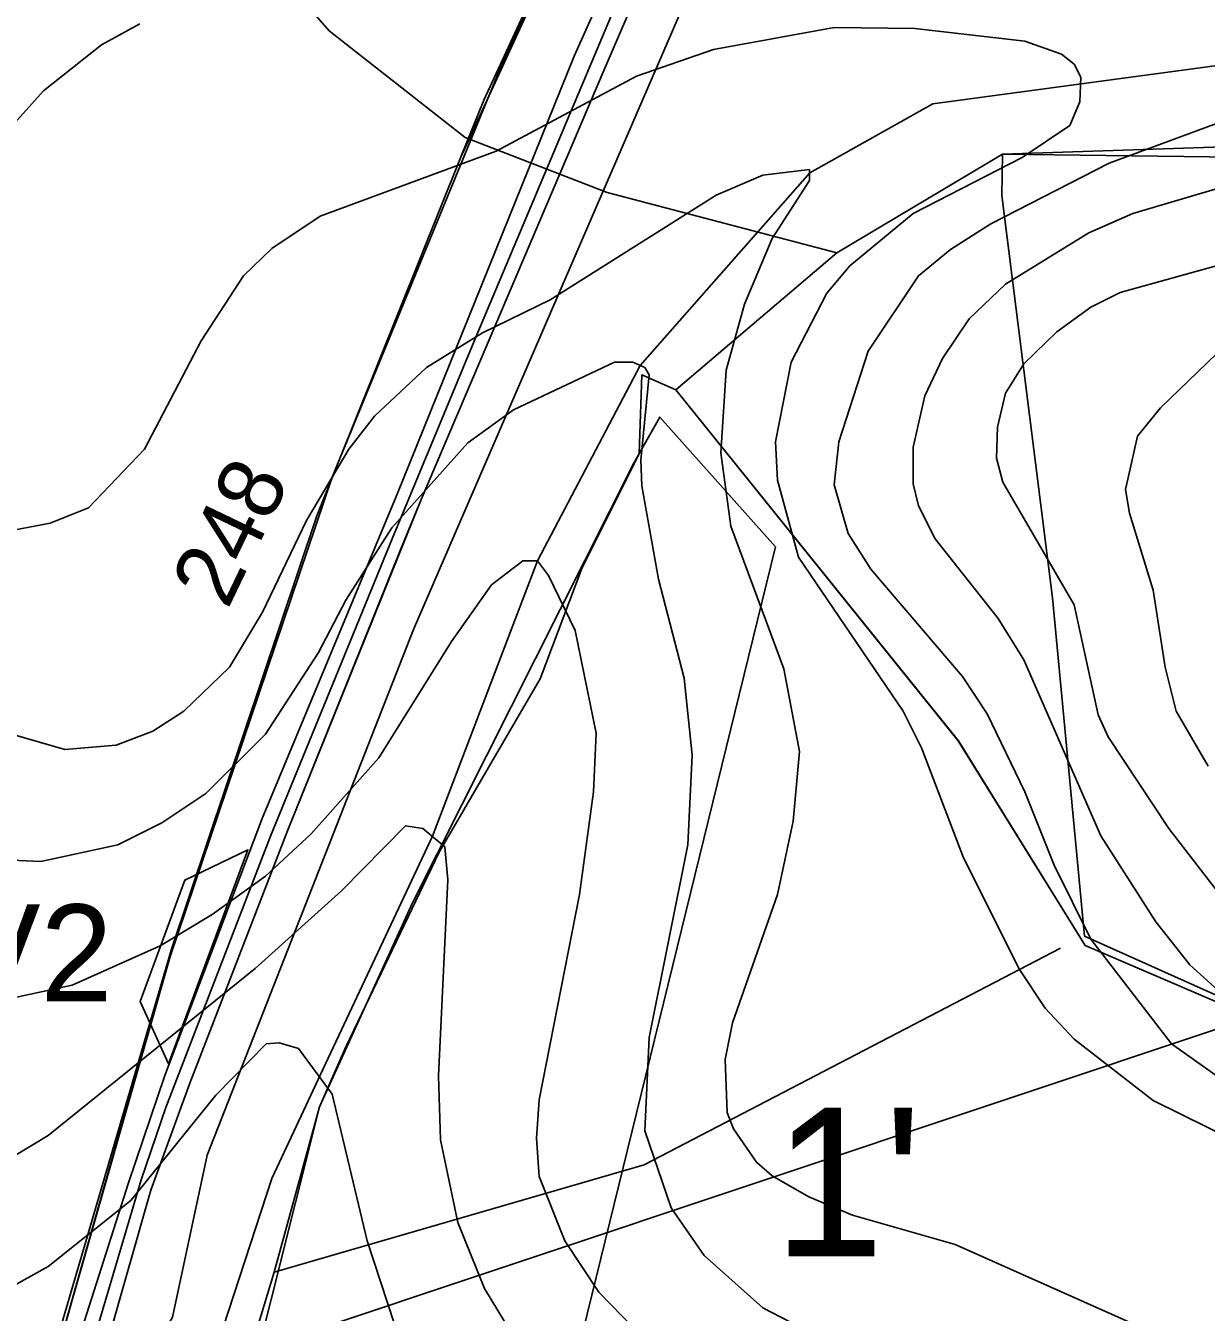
# Model space of a CAD drawing. Extents: x -662500 to -655523, y -1056000 to -1049993.
# Drawn here: x -661073 to -660890.3, y -1051979.7 to -1051780.7 of the extents above; entities that cross this region are included whole.
import ezdxf

# ---------------------------------------------------------------- set-up
doc = ezdxf.new("R2010")
doc.units = 0
for name, color, linetype in [('58', 7, 'Continuous'), ('Vrstva 1', 7, 'Continuous'), ('Vrstva 12', 7, 'Continuous'), ('Vrstva 20', 7, 'Continuous'), ('Vrstva 24', 7, 'Continuous'), ('Vrstva 47', 7, 'Continuous'), ('Vrstva 5', 7, 'Continuous'), ('Vrstva 54', 7, 'Continuous'), ('Vrstva 57', 7, 'Continuous'), ('Vrstva 61', 7, 'Continuous'), ('Vrstva 7', 7, 'Continuous')]:
    doc.layers.add(name, color=color, linetype=linetype)

msp = doc.modelspace()

# ---------------------------------------------------------------- linework, layer by layer
at = {"layer": '58'}
msp.add_lwpolyline([(-661172.54, -1052283.41), (-661170.26, -1052276.87), (-661169, -1052273.86), (-661160.6, -1052250.53), (-661157.7, -1052243.27), (-661155.76, -1052237.73), (-661154.04, -1052229.56), (-661125.66, -1052171.11), (-661116.86, -1052151.73), (-661083.01, -1052058.05), (-661076.06, -1052037.46), (-661076, -1052033.46), (-661076.08, -1052030.47), (-661075.86, -1052018.58), (-661075.98, -1052015.85), (-661075.41, -1052008.86), (-661050.39, -1051923.53), (-661027.93, -1051856.49), (-661005.7, -1051801.13), (-661002.12, -1051792.22), (-660961.54, -1051704.49), (-660954.84, -1051684.73), (-661019.26, -1051651.49)], dxfattribs=at)
at = {"layer": 'Vrstva 1'}
for p, q in [((-660921.87, -1051800.59), (-660816.75, -1051801.98)), ((-660909.2, -1051921.5), (-660840.14, -1051952.57))]:
    msp.add_line(p, q, dxfattribs=at)
for points in [[(-661122.96, -1052165.71), (-661115.78, -1052150.02), (-661075.82, -1052037.15), (-661075.7, -1052033.25), (-661075.53, -1052027.64), (-661075.33, -1052021.14), (-661075.17, -1052015.82), (-661074.99, -1052010.17), (-661050.62, -1051924.66), (-661025.57, -1051850.51), (-660999.68, -1051787.6), (-660960.61, -1051703.03), (-660954.94, -1051684.48), (-661022.97, -1051649.68), (-661088.06, -1051611.98), (-661095.96, -1051608.49), (-661122.36, -1051589.21), (-661159.82, -1051549.46), (-661187.06, -1051518.14), (-661214.68, -1051491.81), (-661250.88, -1051466.71), (-661204.06, -1051402.7), (-661171.31, -1051368.85), (-661098.04, -1051309.04)], [(-660921.87, -1051800.59), (-660921.98, -1051806.97), (-660921.21, -1051813.09), (-660914.16, -1051869.21), (-660909.2, -1051921.5)]]:
    msp.add_lwpolyline(points, dxfattribs=at)
at = {"layer": 'Vrstva 12'}
msp.add_lwpolyline([(-660677.98, -1051748.43), (-660717.94, -1051749.1), (-660749.25, -1051747.86), (-660777.31, -1051745.37), (-660782.46, -1051745.02), (-660790.05, -1051743.6), (-660831.17, -1051734.05), (-660851.28, -1051728.5), (-660881.83, -1051718.2), (-660907.49, -1051707.19), (-660927.4, -1051698.64), (-660936.8, -1051698.75), (-660942.83, -1051699.66), (-660947.81, -1051703.59), (-660954.96, -1051712.4), (-660962.02, -1051729.41), (-660976.83, -1051765.96), (-661003.35, -1051828.87), (-661016.27, -1051860.08), (-661035.12, -1051906.08), (-661051.28, -1051948.02), (-661055.1, -1051959.21), (-661062.47, -1051984.12)], dxfattribs=at)
at = {"layer": 'Vrstva 20'}
msp.add_lwpolyline([(-661046.18, -1052022.33), (-660997.87, -1052027.86), (-660957, -1051861.29), (-660974.89, -1051841.24), (-660978.85, -1051848.26), (-661013.12, -1051916.37), (-661027.54, -1051947.9)], close=True, dxfattribs=at)
at = {"layer": 'Vrstva 24'}
for points in [[(-661325.5, -1051678.5), (-661276.5, -1051675.5), (-661191, -1051668.5), (-661149.5, -1051670), (-661133, -1051674), (-661124.5, -1051677.5), (-661112, -1051684), (-661104.5, -1051691.5), (-661026, -1051781.5), (-661005, -1051798), (-660983, -1051806.5), (-660947.48, -1051815.82)], [(-660947.48, -1051815.82), (-660921.87, -1051800.59), (-660841.03, -1051797.88), (-660812.66, -1051794.62), (-660812.99, -1051801.1), (-660809.04, -1051897.71)], [(-660812.31, -1051961.52), (-660840.14, -1051952.57), (-660909.06, -1051922.97), (-660928.7, -1051891.33), (-660972.42, -1051837.01), (-660947.48, -1051815.82)]]:
    msp.add_lwpolyline(points, dxfattribs=at)
at = {"layer": 'Vrstva 47'}
msp.add_line((-659729.76, -1051549.11), (-661071.93, -1051997.01), dxfattribs=at)
at = {"layer": 'Vrstva 5'}
for points in [[(-661071.7, -1051998.64), (-661050.39, -1051923.53), (-661027.93, -1051856.49), (-661005.7, -1051801.13), (-660960.61, -1051703.03), (-660954.94, -1051684.48), (-661022.97, -1051649.68)], [(-660677.92, -1051746.35), (-660698.73, -1051747.17), (-660725.37, -1051746.94), (-660751.25, -1051745.59), (-660782.88, -1051742.72), (-660796.61, -1051740.39), (-660823.47, -1051733.86), (-660839.84, -1051729.71), (-660861.64, -1051723.47), (-660882.34, -1051716.19), (-660904, -1051706.99), (-660926.53, -1051696.89), (-660937, -1051697), (-660944, -1051698.02), (-660951.11, -1051703.85), (-660956.58, -1051711.68), (-660963.94, -1051729.61), (-660977.17, -1051760.98), (-660988.12, -1051785.41), (-661015.38, -1051852.91), (-661036.37, -1051903.34), (-661051.42, -1051943.05), (-661057.07, -1051959.67), (-661064.71, -1051983.6)], [(-661064.71, -1051983.6), (-661057.07, -1051959.67), (-661051.42, -1051943.05), (-661036.37, -1051903.34), (-661015.38, -1051852.91), (-660988.12, -1051785.41), (-660977.17, -1051760.98), (-660963.94, -1051729.61), (-660956.58, -1051711.68), (-660951.11, -1051703.85), (-660944, -1051698.02), (-660937, -1051697), (-660926.53, -1051696.89), (-660904, -1051706.99), (-660882.34, -1051716.19), (-660861.64, -1051723.47), (-660839.84, -1051729.71), (-660823.47, -1051733.86), (-660796.61, -1051740.39), (-660782.88, -1051742.72), (-660751.25, -1051745.59), (-660725.37, -1051746.94), (-660698.73, -1051747.17), (-660677.92, -1051746.35)], [(-661060.39, -1051984.68), (-661053.63, -1051960.82), (-661047.55, -1051944.24), (-661032.48, -1051905.25), (-661014.87, -1051861.54), (-661011.79, -1051853.99), (-660983.56, -1051787.64), (-660972.73, -1051762.49), (-660960.54, -1051731.01), (-660953.3, -1051713.48), (-660948.2, -1051705.86), (-660942.72, -1051701.59), (-660936.31, -1051700.39), (-660927.8, -1051700.44), (-660905.01, -1051709.79), (-660884.03, -1051719.07)], [(-660884.03, -1051719.07), (-660905.01, -1051709.79), (-660927.8, -1051700.44), (-660936.31, -1051700.39), (-660942.72, -1051701.59), (-660948.2, -1051705.86), (-660953.3, -1051713.48), (-660960.54, -1051731.01), (-660972.73, -1051762.49), (-660983.56, -1051787.64), (-661011.79, -1051853.99), (-661032.48, -1051905.25), (-661047.55, -1051944.24), (-661053.63, -1051960.82), (-661060.39, -1051984.68)], [(-660841.03, -1051797.88), (-660921.87, -1051800.59), (-660947.48, -1051815.82), (-660972.42, -1051837.01), (-660977.65, -1051834.73), (-660978.09, -1051846.9), (-660986.94, -1051864.68), (-660993.38, -1051881.71), (-661009.02, -1051908.52), (-661023.41, -1051938.54), (-661027.54, -1051947.9), (-661034.54, -1051973.5), (-661041.04, -1051994.91)], [(-661041.04, -1051994.91), (-661034.54, -1051973.5), (-661027.54, -1051947.9), (-661023.41, -1051938.54), (-661009.02, -1051908.52), (-660993.38, -1051881.71), (-660986.94, -1051864.68), (-660978.09, -1051846.9), (-660977.65, -1051834.73), (-660972.42, -1051837.01), (-660928.71, -1051891.33), (-660909.06, -1051922.97), (-660840.14, -1051952.57)]]:
    msp.add_lwpolyline(points, dxfattribs=at)
msp.add_lwpolyline([(-660972.42, -1051837.01), (-660947.48, -1051815.82), (-660921.87, -1051800.59), (-660841.03, -1051797.88), (-660812.66, -1051794.62), (-660812.99, -1051801.1), (-660808.94, -1051905.69), (-660807.46, -1051936.49), (-660793.87, -1051937.97), (-660778.91, -1051942.97), (-660777.67, -1051957.47), (-660777.56, -1051972.71), (-660840.14, -1051952.57), (-660909.06, -1051922.97), (-660928.71, -1051891.33)], close=True, dxfattribs=at)
at = {"layer": 'Vrstva 54'}
msp.add_lwpolyline([(-661061.27, -1051999.59), (-661050.24, -1051980.46), (-661044.92, -1051955.41), (-661013, -1051874.07), (-660972.1, -1051779.61), (-660941.44, -1051708.81), (-660929, -1051706.7), (-660806.12, -1051752.81), (-660721.57, -1051764.39), (-660637.41, -1051753.69), (-660533.68, -1051733.93), (-660461.07, -1051720.1)], dxfattribs=at)
at = {"layer": 'Vrstva 57'}
for points in [[(-660700.73, -1051754.78), (-660759.57, -1051766.74), (-660818.96, -1051779.66), (-660856.09, -1051782.51), (-660932.64, -1051792.79), (-660951.67, -1051803.48), (-660977.9, -1051833.27), (-660993.8, -1051863.48), (-661010.03, -1051906.05), (-661027.36, -1051942.94), (-661034.91, -1051959.02), (-661044.14, -1051987.24), (-661052.39, -1052027.89)], [(-660912.88, -1051923.37), (-660977.32, -1051956.9), (-661034.54, -1051973.5)]]:
    msp.add_lwpolyline(points, dxfattribs=at)
at = {"layer": 'Vrstva 61'}
msp.add_lwpolyline([(-661050.86, -1051941.25), (-661055.28, -1051931.61), (-661048.33, -1051912.86), (-661038.6, -1051908.19)], close=True, dxfattribs=at)
at = {"layer": 'Vrstva 7'}
for p, q in [((-661055.31, -1051780.43), (-661061.26, -1051783.69)), ((-660947.89, -1051781), (-660966.59, -1051784.4)), ((-660935.42, -1051781.14), (-660947.89, -1051781)), ((-660918.41, -1051783.13), (-660935.42, -1051781.14)), ((-660912.74, -1051785.11), (-660918.41, -1051783.13)), ((-661061.26, -1051783.69), (-661070.19, -1051790.78)), ((-660966.59, -1051784.4), (-660978.5, -1051788.51)), ((-660910.76, -1051786.67), (-660912.74, -1051785.11)), ((-660909.76, -1051788.65), (-660910.76, -1051786.67)), ((-660978.5, -1051788.51), (-661000.18, -1051800.13)), ((-660909.91, -1051792.48), (-660909.76, -1051788.65)), ((-661070.19, -1051790.78), (-661079.26, -1051800.84)), ((-660911.46, -1051796.16), (-660909.91, -1051792.48)), ((-660905.37, -1051801.98), (-660885.81, -1051794.75)), ((-660918.83, -1051801.12), (-660911.46, -1051796.16)), ((-661000.18, -1051800.13), (-661027.39, -1051810.19)), ((-660935.7, -1051809.77), (-660918.83, -1051801.12)), ((-660958.94, -1051803.82), (-660951.71, -1051802.97)), ((-660958.94, -1051803.82), (-660951.71, -1051802.97)), ((-660951.71, -1051802.97), (-660951.71, -1051804.67)), ((-660951.71, -1051802.97), (-660951.71, -1051804.67)), ((-660923.65, -1051811.33), (-660905.37, -1051801.98)), ((-660901.69, -1051809.77), (-660877.88, -1051802.68)), ((-660966.17, -1051806.94), (-660958.94, -1051803.82)), ((-660966.17, -1051806.94), (-660958.94, -1051803.82)), ((-660951.71, -1051804.67), (-660957.52, -1051813.6)), ((-660951.71, -1051804.67), (-660957.52, -1051813.6)), ((-660991.82, -1051823.09), (-660966.17, -1051806.94)), ((-660991.82, -1051823.09), (-660966.17, -1051806.94)), ((-661027.39, -1051810.19), (-661034.9, -1051815.16)), ((-660945.48, -1051817.85), (-660935.7, -1051809.77)), ((-660908.49, -1051812.75), (-660901.69, -1051809.77)), ((-660929.89, -1051815.3), (-660923.65, -1051811.33)), ((-660921.39, -1051820.68), (-660908.49, -1051812.75)), ((-660957.52, -1051813.6), (-660961.77, -1051823.8)), ((-660957.52, -1051813.6), (-660961.77, -1051823.8)), ((-661034.9, -1051815.16), (-661039.29, -1051819.41)), ((-660934.85, -1051819.41), (-660929.89, -1051815.3)), ((-660903.67, -1051821.96), (-660884.11, -1051816.57)), ((-660949.02, -1051822.1), (-660945.48, -1051817.85)), ((-661039.29, -1051819.41), (-661045.81, -1051829.47)), ((-660942.64, -1051831.03), (-660934.85, -1051819.41)), ((-660927.05, -1051826.07), (-660921.39, -1051820.68)), ((-660954.55, -1051832.73), (-660949.02, -1051822.1)), ((-660908.2, -1051824.23), (-660903.67, -1051821.96)), ((-661002.31, -1051828.19), (-660991.82, -1051823.09)), ((-661002.31, -1051828.19), (-660991.82, -1051823.09)), ((-660961.77, -1051823.8), (-660964.61, -1051834)), ((-660961.77, -1051823.8), (-660964.61, -1051834)), ((-660913.45, -1051828.05), (-660908.2, -1051824.23)), ((-660931.16, -1051832.16), (-660927.05, -1051826.07)), ((-661010.95, -1051833.58), (-661002.31, -1051828.19)), ((-661010.95, -1051833.58), (-661002.31, -1051828.19)), ((-660918.55, -1051833.01), (-660913.45, -1051828.05)), ((-661045.81, -1051829.47), (-661054.6, -1051846.19)), ((-660947.18, -1051845.06), (-660942.64, -1051831.03)), ((-660997.49, -1051840.1), (-660981.9, -1051832.73)), ((-660997.49, -1051840.1), (-660981.9, -1051832.73)), ((-660981.9, -1051832.73), (-660979.06, -1051832.73)), ((-660981.9, -1051832.73), (-660979.06, -1051832.73)), ((-660979.06, -1051832.73), (-660977.22, -1051833.58)), ((-660979.06, -1051832.73), (-660977.22, -1051833.58)), ((-660956.96, -1051845.06), (-660954.55, -1051832.73)), ((-660933.86, -1051837.97), (-660931.16, -1051832.16)), ((-660921.39, -1051837.55), (-660918.55, -1051833.01)), ((-660897.44, -1051839.81), (-660888.79, -1051831.45)), ((-661019.03, -1051841.09), (-661010.95, -1051833.58)), ((-661019.03, -1051841.09), (-661010.95, -1051833.58)), ((-660976.51, -1051834.71), (-660977.79, -1051847.89)), ((-660976.51, -1051834.71), (-660977.79, -1051847.89)), ((-660977.22, -1051833.58), (-660976.51, -1051834.71)), ((-660977.22, -1051833.58), (-660976.51, -1051834.71)), ((-660964.61, -1051834), (-660965.46, -1051846.76)), ((-660964.61, -1051834), (-660965.46, -1051846.76)), ((-660935.7, -1051845.91), (-660933.86, -1051837.97)), ((-660922.66, -1051842.79), (-660921.39, -1051837.55)), ((-661004.57, -1051845.2), (-660997.49, -1051840.1)), ((-661004.57, -1051845.2), (-660997.49, -1051840.1)), ((-660900.98, -1051844.21), (-660897.44, -1051839.81)), ((-661022.99, -1051846.19), (-661019.03, -1051841.09)), ((-661022.99, -1051846.19), (-661019.03, -1051841.09)), ((-660922.8, -1051847.61), (-660922.66, -1051842.79)), ((-660902.82, -1051852.43), (-660900.98, -1051844.21)), ((-661054.6, -1051846.19), (-661063.24, -1051855.26)), ((-661029.51, -1051857.25), (-661022.99, -1051846.19)), ((-661029.51, -1051857.25), (-661022.99, -1051846.19)), ((-661016.33, -1051858.38), (-661004.57, -1051845.2)), ((-661016.33, -1051858.38), (-661004.57, -1051845.2)), ((-660965.46, -1051846.76), (-660963.9, -1051858.09)), ((-660965.46, -1051846.76), (-660963.9, -1051858.09)), ((-660956.67, -1051851.01), (-660956.96, -1051845.06)), ((-660947.89, -1051851.72), (-660947.18, -1051845.06)), ((-660935.7, -1051851.58), (-660935.7, -1051845.91)), ((-660977.79, -1051847.89), (-660977.65, -1051851.86)), ((-660977.79, -1051847.89), (-660977.65, -1051851.86)), ((-660921.81, -1051851.29), (-660922.8, -1051847.61)), ((-660977.65, -1051851.86), (-660975.09, -1051866.31)), ((-660977.65, -1051851.86), (-660975.09, -1051866.31)), ((-660953.41, -1051862.91), (-660956.67, -1051851.01)), ((-660945.76, -1051859.23), (-660947.89, -1051851.72)), ((-660934.85, -1051854.98), (-660935.7, -1051851.58)), ((-660910.76, -1051870.28), (-660921.81, -1051851.29)), ((-660902.25, -1051856.11), (-660902.82, -1051852.43)), ((-661063.24, -1051855.26), (-661069.2, -1051857.67)), ((-660932.3, -1051860.08), (-660934.85, -1051854.98)), ((-660898.57, -1051868.02), (-660902.25, -1051856.11)), ((-661069.2, -1051857.67), (-661074.58, -1051858.66)), ((-661036.32, -1051871.42), (-661029.51, -1051857.25)), ((-661036.32, -1051871.42), (-661029.51, -1051857.25)), ((-661023.42, -1051869.57), (-661016.33, -1051858.38)), ((-661023.42, -1051869.57), (-661016.33, -1051858.38)), ((-660963.9, -1051858.09), (-660955.68, -1051880.2)), ((-660963.9, -1051858.09), (-660955.68, -1051880.2)), ((-660942.22, -1051864.76), (-660945.76, -1051859.23)), ((-660922.52, -1051872.41), (-660932.3, -1051860.08)), ((-660996.07, -1051863.48), (-661000.89, -1051867.17)), ((-660993.8, -1051863.48), (-660996.07, -1051863.48)), ((-660992.1, -1051865.75), (-660993.8, -1051863.48)), ((-660937.26, -1051886.72), (-660953.41, -1051862.91)), ((-660928.05, -1051881.34), (-660942.22, -1051864.76)), ((-660987.99, -1051874.25), (-660992.1, -1051865.75)), ((-660975.09, -1051866.31), (-660971.13, -1051881.62)), ((-660975.09, -1051866.31), (-660971.13, -1051881.62)), ((-661000.89, -1051867.17), (-661007.12, -1051875.95)), ((-660896.73, -1051879.92), (-660898.57, -1051868.02)), ((-661027.67, -1051877.65), (-661023.42, -1051869.57)), ((-661027.67, -1051877.65), (-661023.42, -1051869.57)), ((-660907.07, -1051887.29), (-660910.76, -1051870.28)), ((-661041.42, -1051879.92), (-661036.32, -1051871.42)), ((-661041.42, -1051879.92), (-661036.32, -1051871.42)), ((-660918.55, -1051878.79), (-660922.52, -1051872.41)), ((-660984.73, -1051890.12), (-660987.99, -1051874.25)), ((-661007.12, -1051875.95), (-661018.32, -1051893.95)), ((-661035.89, -1051890.26), (-661027.67, -1051877.65)), ((-661035.89, -1051890.26), (-661027.67, -1051877.65)), ((-661048.51, -1051886.72), (-661041.42, -1051879.92)), ((-661048.51, -1051886.72), (-661041.42, -1051879.92)), ((-660955.68, -1051880.2), (-660953.27, -1051892.96)), ((-660955.68, -1051880.2), (-660953.27, -1051892.96)), ((-660906.65, -1051906), (-660918.55, -1051878.79)), ((-660895.03, -1051886.72), (-660896.73, -1051879.92)), ((-660971.13, -1051881.62), (-660969.85, -1051893.52)), ((-660971.13, -1051881.62), (-660969.85, -1051893.52)), ((-660924.22, -1051887.15), (-660928.05, -1051881.34)), ((-661053.32, -1051889.84), (-661048.51, -1051886.72)), ((-661053.32, -1051889.84), (-661048.51, -1051886.72)), ((-660934.42, -1051892.39), (-660937.26, -1051886.72)), ((-660890.07, -1051895.23), (-660895.03, -1051886.72)), ((-660918.41, -1051899.19), (-660924.22, -1051887.15)), ((-660905.51, -1051890.69), (-660907.07, -1051887.29)), ((-661077.13, -1051889.7), (-661066.93, -1051892.67)), ((-661077.13, -1051889.7), (-661066.93, -1051892.67)), ((-661058.99, -1051891.97), (-661053.32, -1051889.84)), ((-661058.99, -1051891.97), (-661053.32, -1051889.84)), ((-661045.1, -1051899.48), (-661035.89, -1051890.26)), ((-661045.1, -1051899.48), (-661035.89, -1051890.26)), ((-660985.16, -1051899.19), (-660984.73, -1051890.12)), ((-660896.16, -1051904.86), (-660905.51, -1051890.69)), ((-661066.93, -1051892.67), (-661058.99, -1051891.97)), ((-661066.93, -1051892.67), (-661058.99, -1051891.97)), ((-660927.9, -1051909.4), (-660934.42, -1051892.39)), ((-661018.32, -1051893.95), (-661028.81, -1051905.71)), ((-660969.85, -1051893.52), (-660970.56, -1051907.41)), ((-660969.85, -1051893.52), (-660970.56, -1051907.41)), ((-660953.27, -1051892.96), (-660954.26, -1051903.73)), ((-660953.27, -1051892.96), (-660954.26, -1051903.73)), ((-661051.91, -1051904.01), (-661045.1, -1051899.48)), ((-661051.91, -1051904.01), (-661045.1, -1051899.48)), ((-660987.28, -1051915.06), (-660985.16, -1051899.19)), ((-660913.87, -1051910.53), (-660918.41, -1051899.19)), ((-661058.71, -1051907.41), (-661051.91, -1051904.01)), ((-661058.71, -1051907.41), (-661051.91, -1051904.01)), ((-661014.21, -1051904.44), (-661024.13, -1051914.5)), ((-661011.52, -1051904.86), (-661014.21, -1051904.44)), ((-660954.26, -1051903.73), (-660956.67, -1051915.06)), ((-660954.26, -1051903.73), (-660956.67, -1051915.06)), ((-661028.81, -1051905.71), (-661035.89, -1051912.23)), ((-661008.11, -1051907.7), (-661011.52, -1051904.86)), ((-660898.14, -1051919.32), (-660906.65, -1051906)), ((-660885.67, -1051918.47), (-660896.16, -1051904.86)), ((-661070.61, -1051909.96), (-661058.71, -1051907.41)), ((-661070.61, -1051909.96), (-661058.71, -1051907.41)), ((-661007.69, -1051912.8), (-661008.11, -1051907.7)), ((-660970.56, -1051907.41), (-660976.51, -1051937.17)), ((-660970.56, -1051907.41), (-660976.51, -1051937.17)), ((-661077.42, -1051909.68), (-661070.61, -1051909.96)), ((-661077.42, -1051909.68), (-661070.61, -1051909.96)), ((-660919.26, -1051926.69), (-660927.9, -1051909.4)), ((-660908.2, -1051922.01), (-660913.87, -1051910.53)), ((-661035.89, -1051912.23), (-661044.11, -1051918.18)), ((-661024.13, -1051914.5), (-661037.45, -1051926.54)), ((-661009.11, -1051943.12), (-661007.69, -1051912.8)), ((-660993.52, -1051946.81), (-660987.28, -1051915.06)), ((-660956.67, -1051915.06), (-660963.62, -1051934.91)), ((-660956.67, -1051915.06), (-660963.62, -1051934.91)), ((-661044.11, -1051918.18), (-661052.19, -1051923)), ((-660892.9, -1051925.98), (-660898.14, -1051919.32)), ((-660895.73, -1051938.17), (-660908.2, -1051922.01)), ((-661052.19, -1051923), (-661065.79, -1051929.09)), ((-660885.53, -1051932.64), (-660892.9, -1051925.98)), ((-661037.45, -1051926.54), (-661069.48, -1051952.34)), ((-660915.29, -1051932.64), (-660919.26, -1051926.69)), ((-661065.79, -1051929.09), (-661074.86, -1051931.08)), ((-660910.76, -1051937.46), (-660915.29, -1051932.64)), ((-660963.62, -1051934.91), (-660964.75, -1051940.57)), ((-660963.62, -1051934.91), (-660964.75, -1051940.57)), ((-661043.54, -1051946.1), (-661035.75, -1051938.16)), ((-661035.75, -1051938.16), (-661033.77, -1051938.02)), ((-661033.77, -1051938.02), (-661030.79, -1051938.87)), ((-660976.51, -1051937.17), (-660977.22, -1051951.63)), ((-660976.51, -1051937.17), (-660977.22, -1051951.63)), ((-660898.57, -1051946.95), (-660910.76, -1051937.46)), ((-660887.37, -1051944.12), (-660895.73, -1051938.17)), ((-661030.79, -1051938.87), (-661025.55, -1051945.96)), ((-660964.75, -1051940.57), (-660964.47, -1051948.79)), ((-660964.75, -1051940.57), (-660964.47, -1051948.79)), ((-661008.82, -1051953.04), (-661009.11, -1051943.12)), ((-661056.72, -1051962.4), (-661043.54, -1051946.1)), ((-661025.55, -1051945.96), (-661020.16, -1051968.63)), ((-660993.94, -1051952.76), (-660993.52, -1051946.81)), ((-660881, -1051955.6), (-660898.57, -1051946.95)), ((-660964.47, -1051948.79), (-660963.47, -1051951.34)), ((-660964.47, -1051948.79), (-660963.47, -1051951.34)), ((-661069.48, -1051952.34), (-661077.7, -1051957.3)), ((-660977.22, -1051951.63), (-660973.11, -1051963.53)), ((-660977.22, -1051951.63), (-660973.11, -1051963.53)), ((-660963.47, -1051951.34), (-660959.93, -1051956.45)), ((-660963.47, -1051951.34), (-660959.93, -1051956.45)), ((-661006.13, -1051965.8), (-661008.82, -1051953.04)), ((-660993.52, -1051958.71), (-660993.94, -1051952.76)), ((-660959.93, -1051956.45), (-660957.52, -1051958.57)), ((-660959.93, -1051956.45), (-660957.52, -1051958.57)), ((-660989.55, -1051968.63), (-660993.52, -1051958.71)), ((-660957.52, -1051958.57), (-660951.85, -1051961.83)), ((-660957.52, -1051958.57), (-660951.85, -1051961.83)), ((-660951.85, -1051961.83), (-660945.05, -1051964.67)), ((-660951.85, -1051961.83), (-660945.05, -1051964.67)), ((-661069.48, -1051972.6), (-661056.72, -1051962.4)), ((-660973.11, -1051963.53), (-660968.01, -1051970.9)), ((-660973.11, -1051963.53), (-660968.01, -1051970.9)), ((-661002.02, -1051976), (-661006.13, -1051965.8)), ((-660945.05, -1051964.67), (-660929.18, -1051969.2)), ((-660945.05, -1051964.67), (-660929.18, -1051969.2)), ((-661020.16, -1051968.63), (-661015.91, -1051981.53)), ((-660984.31, -1051976.57), (-660989.55, -1051968.63)), ((-660929.18, -1051969.2), (-660890.63, -1051986.35)), ((-660929.18, -1051969.2), (-660890.63, -1051986.35)), ((-660968.01, -1051970.9), (-660958.94, -1051978.98)), ((-660968.01, -1051970.9), (-660958.94, -1051978.98)), ((-661074.86, -1051975.58), (-661069.48, -1051972.6)), ((-660998.9, -1051981.1), (-661002.02, -1051976)), ((-660972.69, -1051988.47), (-660984.31, -1051976.57)), ((-660958.94, -1051978.98), (-660943.63, -1051986.92)), ((-660958.94, -1051978.98), (-660943.63, -1051986.92))]:
    msp.add_line(p, q, dxfattribs=at)

# ---------------------------------------------------------------- texts
at = {"layer": 'Vrstva 57'}
msp.add_text("1'", height=23, dxfattribs=at).set_placement((-660957.29, -1051971.03))
at = {"layer": 'Vrstva 61'}
msp.add_text('V2', height=15, dxfattribs=at).set_placement((-661084.06, -1051931.62))
at = {"layer": 'Vrstva 7'}
msp.add_text('248', height=10, rotation=64.356, dxfattribs=at).set_placement((-661041.74, -1051871.15))

doc.saveas('drawing.dxf')
